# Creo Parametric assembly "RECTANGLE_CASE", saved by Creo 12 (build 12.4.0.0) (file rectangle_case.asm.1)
Units: Inch lbm Second (Pro/E Default); INCH, POUND, SECS

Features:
  1. datum plane "ASM_RIGHT"
  2. datum plane "ASM_TOP"
  3. datum plane "ASM_FRONT"
  4. coordinate system
  5. component "BOTTOM_RECTANGLE_CASE"
  6. component "TOP_RECTANGLE_CASE"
